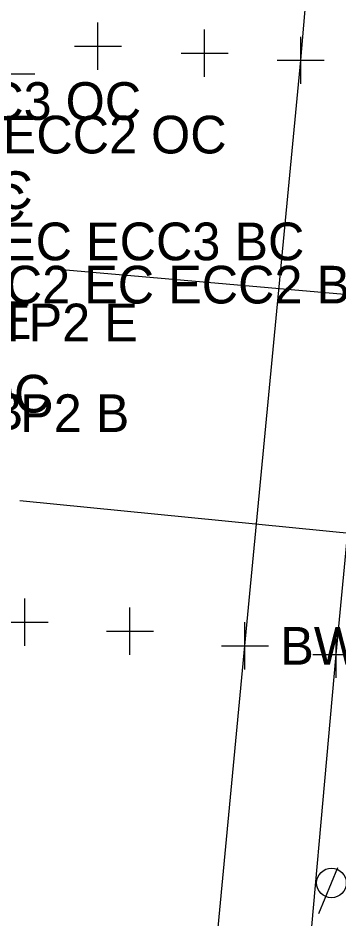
# Model space of a CAD drawing. Extents: x 1363693 to 1365209, y 422201 to 424153.
# Drawn here: x 1364244.28 to 1364257.92, y 423503.66 to 423541.91 of the extents above; entities that cross this region are included whole.
import ezdxf

# ---------------------------------------------------------------- set-up
doc = ezdxf.new("R2010")
doc.units = 0
for name, color, linetype in [('O-ALGN-TEXT-BASELINE-WERK-CL-RW', 7, 'Continuous'), ('SV_X_Original_Ground', 7, 'Continuous'), ('SV_X_Random_Point', 7, 'Continuous'), ('SV_X_Shot_Marker', 7, 'Continuous'), ('UT_X_Gas', 7, 'Continuous'), ('UT_X_Unknown_Cells', 7, 'Continuous'), ('UT_X_Water', 7, 'Continuous')]:
    doc.layers.add(name, color=color, linetype=linetype)

msp = doc.modelspace()

# ---------------------------------------------------------------- linework, layer by layer
at = {"layer": 'O-ALGN-TEXT-BASELINE-WERK-CL-RW'}
for points in [[(1364246.856, 423440.603), (1364248.104, 423453.853), (1364248.377, 423456.684), (1364249.2, 423465.481), (1364251.088, 423485.954), (1364251.263, 423487.647), (1364251.52, 423490.318), (1364252.027, 423495.547), (1364252.167, 423496.873), (1364253.921, 423515.258), (1364256.29, 423540.114), (1364256.554, 423543.102), (1364257.462, 423552.231), (1364258.571, 423564.887)], [(1364250.844, 423440.28), (1364253.104, 423465.04), (1364254.818, 423484.4), (1364255.369, 423489.96), (1364256.279, 423497.969), (1364257.799, 423514.897), (1364260.179, 423539.822), (1364260.288, 423541.243), (1364261.35, 423553.084), (1364262.514, 423564.616)]]:
    msp.add_lwpolyline(points, dxfattribs=at)
at = {"layer": 'SV_X_Original_Ground'}
for p, q in [((1364247.676, 423539.715), (1364247.676, 423541.715)), ((1364252.207, 423539.418), (1364252.207, 423541.418)), ((1364246.676, 423540.715), (1364248.676, 423540.715)), ((1364251.207, 423540.418), (1364253.207, 423540.418)), ((1364242.993, 423539.541), (1364244.993, 423539.541)), ((1364244.564, 423515.265), (1364244.564, 423517.265)), ((1364249.037, 423514.881), (1364249.037, 423516.881)), ((1364243.564, 423516.265), (1364245.564, 423516.265)), ((1364248.037, 423515.881), (1364250.037, 423515.881))]:
    msp.add_line(p, q, dxfattribs=at)
at = {"layer": 'SV_X_Shot_Marker'}
for p, q in [((1364256.29, 423539.114), (1364256.29, 423541.114)), ((1364255.29, 423540.114), (1364257.29, 423540.114)), ((1364253.921, 423514.258), (1364253.921, 423516.258)), ((1364257.799, 423513.897), (1364257.799, 423515.897)), ((1364252.921, 423515.258), (1364254.921, 423515.258)), ((1364256.799, 423514.897), (1364258.799, 423514.897))]:
    msp.add_line(p, q, dxfattribs=at)
at = {"layer": 'UT_X_Gas'}
msp.add_line((1364265.183, 423519.354), (1364244.357, 423521.42), dxfattribs=at)
at = {"layer": 'UT_X_Unknown_Cells'}
msp.add_line((1364257.063, 423503.898), (1364257.866, 423505.843), dxfattribs=at)
msp.add_circle((1364257.597, 423505.192), 0.63, dxfattribs=at)
at = {"layer": 'UT_X_Water'}
msp.add_line((1364245.657, 423531.281), (1364300.863, 423526.417), dxfattribs=at)

# ---------------------------------------------------------------- texts
at = {"layer": 'SV_X_Random_Point'}
for s, p in [('FWL EC E CR2 C', (1364227.786, 423533.802)), ('TWL EC E CR2 C', (1364227.488, 423533.264))]:
    msp.add_text(s, height=1.6, dxfattribs=at).set_placement(p)
at = {"layer": 'SV_X_Shot_Marker'}
for s, p in [('ECC3 OC', (1364240.001, 423537.585)), ('ECC2 OC', (1364243.631, 423536.16)), ('ECC3 EC ECC3 BC', (1364237.301, 423531.626)), ('ECC2 EC ECC2 BC', (1364240.788, 423529.791)), ('ECC1 C STP1 E', (1364229.046, 423528.281)), ('ECC3 B BC STP2 E', (1364230.106, 423528.184)), ('ECC2 OC', (1364236.144, 423525.162)), ('ECC1 C STP1 B', (1364228.69, 423524.415)), ('ECC2 B BC STP2 B', (1364229.745, 423524.334)), ('BW1 C', (1364255.421, 423514.458))]:
    msp.add_text(s, height=1.6, dxfattribs=at).set_placement(p)

doc.saveas('drawing.dxf')
